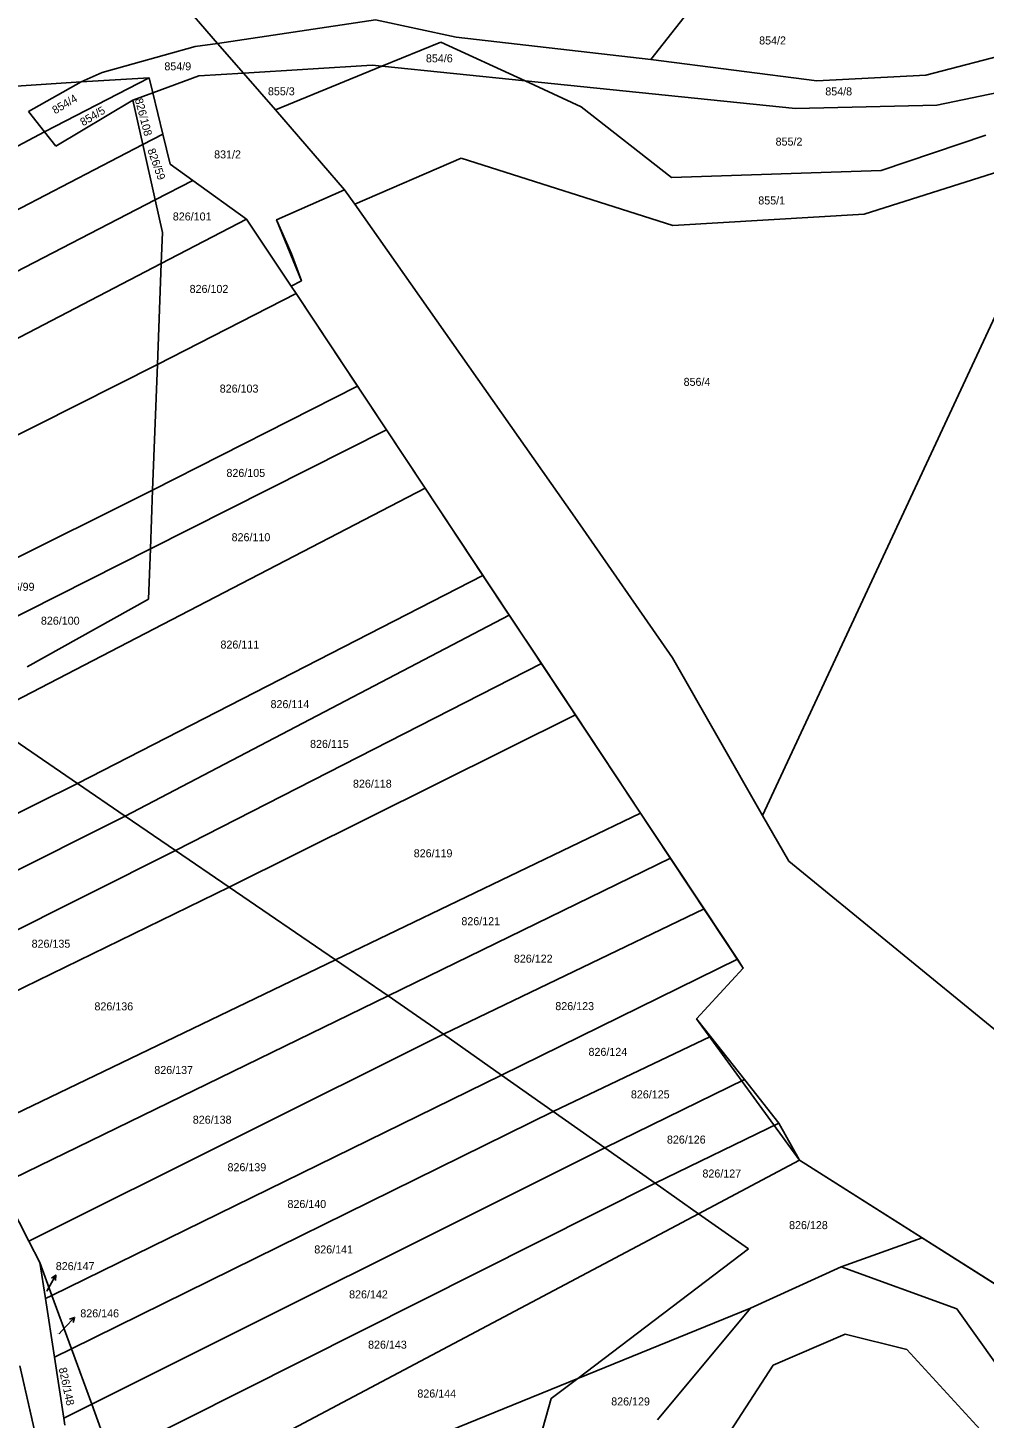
# Model space of a CAD drawing. Extents: x -593358 to -590116, y -1072518 to -1068420.
# Drawn here: x -592835.7 to -592632.7, y -1070925.3 to -1070630 of the extents above; entities that cross this region are included whole.
import ezdxf

# ---------------------------------------------------------------- set-up
doc = ezdxf.new("R2010")
doc.units = 0
for name, color, linetype in [('katastrální hranice', 7, 'Continuous'), ('lesy', 7, 'Continuous'), ('Parcela KN', 7, 'Continuous'), ('Parcela ZE', 7, 'Continuous'), ('Parcelní číslo', 7, 'Continuous'), ('vnější obvod_šetřený', 7, 'Continuous'), ('Vrstva 16', 7, 'Continuous')]:
    doc.layers.add(name, color=color, linetype=linetype)

msp = doc.modelspace()

# ---------------------------------------------------------------- linework, layer by layer
at = {"layer": 'katastrální hranice'}
msp.add_line((-592832.3, -1070936.59), (-592837.43, -1070914.17), dxfattribs=at)
at = {"layer": 'lesy'}
msp.add_line((-592778.79, -1070686.39), (-592779.83, -1070684.82), dxfattribs=at)
for points in [[(-592768.48, -1070664.38), (-592775.7, -1070667.555), (-592782.92, -1070670.73), (-592779.745, -1070677.95), (-592777.66, -1070683.7), (-592779.83, -1070684.82)], [(-592370.8, -1070941.28), (-592400.84, -1070929.68), (-592419.44, -1070939.96), (-592446.39, -1070946.25), (-592467.72, -1070944.19), (-592483.05, -1070937.18), (-592529.51, -1070942.3), (-592554.86, -1070932.86), (-592614.5, -1070906.86), (-592671.86, -1070870.49), (-592693.73, -1070840.44), (-592683.82, -1070829.7), (-592778.79, -1070686.39), (-592778.79, -1070686.39)]]:
    msp.add_lwpolyline(points, dxfattribs=at)
at = {"layer": 'Parcela KN'}
for p, q in [((-592814.19, -1070611.7), (-592795.43, -1070633.27)), ((-592688.83, -1070618.05), (-592703.45, -1070636.69)), ((-592795.43, -1070633.27), (-592761.93, -1070628.28)), ((-592744.82, -1070631.95), (-592761.93, -1070628.28)), ((-592645.05, -1070640.06), (-592598.34, -1070627.73)), ((-592795.43, -1070633.27), (-592800.23, -1070633.94)), ((-592703.45, -1070636.69), (-592744.82, -1070631.95)), ((-592800.23, -1070633.94), (-592819.94, -1070639.44)), ((-592789.95, -1070639.59), (-592762.64, -1070637.93)), ((-592762.64, -1070637.93), (-592760.55, -1070638.14)), ((-592760.55, -1070638.14), (-592730.16, -1070641.24)), ((-592703.45, -1070636.69), (-592668.22, -1070641.23)), ((-592840.32, -1070642.49), (-592824.4, -1070641.48)), ((-592824.4, -1070641.48), (-592835.61, -1070647.78)), ((-592819.94, -1070639.44), (-592824.4, -1070641.48)), ((-592809.19, -1070643.8), (-592799.44, -1070640.17)), ((-592799.44, -1070640.17), (-592789.95, -1070639.59)), ((-592789.95, -1070639.59), (-592783.18, -1070647.4)), ((-592730.16, -1070641.24), (-592672.73, -1070647.11)), ((-592668.22, -1070641.23), (-592645.05, -1070640.06)), ((-592642.73, -1070646.39), (-592617.04, -1070641.03)), ((-592813.42, -1070645.37), (-592809.19, -1070643.8)), ((-592807.05, -1070652.56), (-592809.19, -1070643.8)), ((-592835.61, -1070647.78), (-592832.17, -1070652.1)), ((-592829.78, -1070655.1), (-592813.42, -1070645.37)), ((-592813.42, -1070645.37), (-592811.32, -1070654.78)), ((-592783.18, -1070647.4), (-592768.48, -1070664.38)), ((-592672.73, -1070647.11), (-592642.73, -1070646.39)), ((-592832.17, -1070652.1), (-592829.78, -1070655.1)), ((-592805.49, -1070658.95), (-592807.05, -1070652.56)), ((-592811.32, -1070654.78), (-592808.7, -1070666.5)), ((-592800.73, -1070662.38), (-592805.49, -1070658.95)), ((-592743.74, -1070657.65), (-592766.33, -1070667.44)), ((-592698.8, -1070671.94), (-592743.74, -1070657.65)), ((-592789.31, -1070670.6), (-592800.73, -1070662.38)), ((-592629.39, -1070660.44), (-592658.18, -1070669.56)), ((-592768.48, -1070664.38), (-592782.92, -1070670.73)), ((-592768.48, -1070664.38), (-592766.33, -1070667.44)), ((-592808.7, -1070666.5), (-592807.14, -1070673.46)), ((-592766.33, -1070667.44), (-592719.62, -1070733.92)), ((-592779.83, -1070684.82), (-592789.31, -1070670.6)), ((-592782.92, -1070670.73), (-592777.66, -1070683.7)), ((-592658.18, -1070669.56), (-592698.8, -1070671.94)), ((-592807.14, -1070673.46), (-592807.39, -1070680.01)), ((-592807.39, -1070680.01), (-592808.2, -1070701.51)), ((-592777.66, -1070683.7), (-592779.83, -1070684.82)), ((-592779.83, -1070684.82), (-592778.79, -1070686.39)), ((-592778.79, -1070686.39), (-592765.73, -1070706.1)), ((-592808.2, -1070701.51), (-592809.23, -1070728.16)), ((-592765.73, -1070706.1), (-592759.61, -1070715.34)), ((-592759.61, -1070715.34), (-592751.39, -1070727.74)), ((-592751.39, -1070727.74), (-592739.1, -1070746.28)), ((-592809.23, -1070728.16), (-592809.7, -1070740.64)), ((-592719.62, -1070733.92), (-592698.84, -1070763.82)), ((-592809.7, -1070740.64), (-592810.11, -1070751.36)), ((-592739.1, -1070746.28), (-592733.5, -1070754.73)), ((-592810.11, -1070751.36), (-592835.85, -1070765.67)), ((-592733.5, -1070754.73), (-592726.68, -1070765.02)), ((-592726.68, -1070765.02), (-592719.48, -1070775.89)), ((-592698.84, -1070763.82), (-592679.76, -1070797.26)), ((-592825.15, -1070790.5), (-592845.5, -1070776.58)), ((-592719.48, -1070775.89), (-592705.62, -1070796.8)), ((-592815.08, -1070797.39), (-592825.15, -1070790.5)), ((-592804.37, -1070804.72), (-592815.08, -1070797.39)), ((-592705.62, -1070796.8), (-592699.28, -1070806.36)), ((-592679.76, -1070797.26), (-592674.19, -1070807.01)), ((-592792.97, -1070812.52), (-592804.37, -1070804.72)), ((-592699.28, -1070806.36), (-592692.16, -1070817.1)), ((-592674.19, -1070807.01), (-592629.89, -1070843.2)), ((-592770.39, -1070827.96), (-592792.97, -1070812.52)), ((-592692.16, -1070817.1), (-592685.06, -1070827.82)), ((-592759.25, -1070835.58), (-592770.39, -1070827.96)), ((-592685.06, -1070827.82), (-592683.82, -1070829.7)), ((-592683.82, -1070829.7), (-592693.73, -1070840.44)), ((-592754.1, -1070839.11), (-592759.25, -1070835.58)), ((-592747.5, -1070843.75), (-592754.1, -1070839.11)), ((-592693.73, -1070840.44), (-592690.76, -1070844.22)), ((-592735.19, -1070852.41), (-592747.5, -1070843.75)), ((-592690.76, -1070844.22), (-592683.56, -1070853.35)), ((-592724.18, -1070860.16), (-592735.19, -1070852.41)), ((-592683.56, -1070853.35), (-592676.25, -1070862.63)), ((-592713.22, -1070867.87), (-592724.18, -1070860.16)), ((-592676.25, -1070862.63), (-592671.86, -1070870.49)), ((-592702.55, -1070875.37), (-592713.22, -1070867.87)), ((-592671.86, -1070870.49), (-592645.86, -1070886.98)), ((-592693.32, -1070881.86), (-592702.55, -1070875.37)), ((-592835.52, -1070887.66), (-592841.69, -1070875.75)), ((-592682.7, -1070889.33), (-592693.32, -1070881.86)), ((-592645.86, -1070886.98), (-592614.5, -1070906.86)), ((-592833.16, -1070892.21), (-592835.52, -1070887.66)), ((-592718.96, -1070916.83), (-592682.7, -1070889.33)), ((-592833.16, -1070892.21), (-592830.61, -1070899.2)), ((-592831.98, -1070899.87), (-592833.16, -1070892.21)), ((-592682.28, -1070901.89), (-592663.07, -1070893.11)), ((-592663.07, -1070893.11), (-592638.47, -1070902.03)), ((-592830.07, -1070912.31), (-592831.98, -1070899.87)), ((-592830.61, -1070899.2), (-592826.46, -1070910.55)), ((-592702.07, -1070925.64), (-592682.28, -1070901.89)), ((-592638.47, -1070902.03), (-592623.05, -1070923.78)), ((-592677.46, -1070914), (-592662.19, -1070907.44)), ((-592662.19, -1070907.44), (-592649.13, -1070910.72)), ((-592826.46, -1070910.55), (-592822.17, -1070922.3)), ((-592649.13, -1070910.72), (-592621.72, -1070940.48)), ((-592828.08, -1070925.25), (-592830.07, -1070912.31)), ((-592724.64, -1070921.14), (-592718.96, -1070916.83)), ((-592677.46, -1070914), (-592692.75, -1070937.56)), ((-592822.17, -1070922.3), (-592818.1, -1070933.46)), ((-592738.55, -1070970.14), (-592724.64, -1070921.14)), ((-592827.84, -1070926.78), (-592828.08, -1070925.25))]:
    msp.add_line(p, q, dxfattribs=at)
at = {"layer": 'Parcela ZE'}
for p, q in [((-592795.43, -1070633.27), (-592789.95, -1070639.59)), ((-592748.05, -1070633.03), (-592760.55, -1070638.14)), ((-592730.16, -1070641.24), (-592748.05, -1070633.03)), ((-592760.55, -1070638.14), (-592783.18, -1070647.4)), ((-592832.17, -1070652.1), (-592809.98, -1070640.57)), ((-592824.4, -1070641.48), (-592809.98, -1070640.57)), ((-592809.98, -1070640.57), (-592809.19, -1070643.8)), ((-592718.23, -1070646.72), (-592730.16, -1070641.24)), ((-592606.92, -1070640.8), (-592679.76, -1070797.26)), ((-592699.07, -1070661.8), (-592718.23, -1070646.72)), ((-592959.9, -1070719.35), (-592832.17, -1070652.1)), ((-592811.32, -1070654.78), (-592807.05, -1070652.56)), ((-592632.31, -1070652.79), (-592654.56, -1070660.28)), ((-592952.08, -1070727.97), (-592811.32, -1070654.78)), ((-592808.7, -1070666.5), (-592800.73, -1070662.38)), ((-592654.56, -1070660.28), (-592699.07, -1070661.8)), ((-592945.68, -1070737.38), (-592808.7, -1070666.5)), ((-592807.39, -1070680.01), (-592789.31, -1070670.6)), ((-592938.93, -1070748.45), (-592807.39, -1070680.01)), ((-592808.2, -1070701.51), (-592778.79, -1070686.39)), ((-592897.8, -1070746.67), (-592808.2, -1070701.51)), ((-592809.23, -1070728.16), (-592765.73, -1070706.1)), ((-592809.7, -1070740.64), (-592759.61, -1070715.34)), ((-592845.5, -1070776.58), (-592751.39, -1070727.74)), ((-592874.2, -1070760.59), (-592809.23, -1070728.16)), ((-592852.99, -1070762.5), (-592809.7, -1070740.64)), ((-592739.1, -1070746.28), (-592825.15, -1070790.5)), ((-592733.5, -1070754.73), (-592815.08, -1070797.39)), ((-592804.37, -1070804.72), (-592726.68, -1070765.02)), ((-592792.97, -1070812.52), (-592719.48, -1070775.89)), ((-592825.15, -1070790.5), (-592876.55, -1070815.8)), ((-592815.08, -1070797.39), (-592870.28, -1070825.11)), ((-592770.39, -1070827.96), (-592705.62, -1070796.8)), ((-592863.9, -1070834.59), (-592804.37, -1070804.72)), ((-592759.25, -1070835.58), (-592699.28, -1070806.36)), ((-592858.04, -1070844.18), (-592792.97, -1070812.52)), ((-592747.5, -1070843.75), (-592692.16, -1070817.1)), ((-592847.28, -1070864.95), (-592770.39, -1070827.96)), ((-592685.06, -1070827.82), (-592735.19, -1070852.41)), ((-592841.69, -1070875.75), (-592759.25, -1070835.58)), ((-592835.52, -1070887.66), (-592747.5, -1070843.75)), ((-592690.76, -1070844.22), (-592724.18, -1070860.16)), ((-592735.19, -1070852.41), (-592830.61, -1070899.2)), ((-592683.56, -1070853.35), (-592713.22, -1070867.87)), ((-592724.18, -1070860.16), (-592826.46, -1070910.55)), ((-592676.25, -1070862.63), (-592702.55, -1070875.37)), ((-592713.22, -1070867.87), (-592822.17, -1070922.3)), ((-592671.86, -1070870.49), (-592693.32, -1070881.86)), ((-592702.55, -1070875.37), (-592818.1, -1070933.46)), ((-592693.32, -1070881.86), (-592813.66, -1070945.62)), ((-592663.07, -1070893.11), (-592645.86, -1070886.98)), ((-592830.61, -1070899.2), (-592831.98, -1070899.87)), ((-592718.96, -1070916.83), (-592682.28, -1070901.89)), ((-592826.46, -1070910.55), (-592830.07, -1070912.31)), ((-592774.9, -1070939.62), (-592718.96, -1070916.83)), ((-592822.17, -1070922.3), (-592828.08, -1070925.25))]:
    msp.add_line(p, q, dxfattribs=at)
at = {"layer": 'vnější obvod_šetřený'}
msp.add_line((-592837.43, -1070914.17), (-592834.865, -1070925.38), dxfattribs=at)
at = {"layer": 'Vrstva 16'}
for p, q in [((-592829.795, -1070894.908), (-592831.27, -1070897.52)), ((-592831.71, -1070898.31), (-592831.27, -1070897.52)), ((-592825.818, -1070903.871), (-592827.87, -1070906.06)), ((-592829.11, -1070907.38), (-592827.87, -1070906.06))]:
    msp.add_line(p, q, dxfattribs=at)
for points in [[(-592830.722, -1070895.533), (-592829.795, -1070894.908), (-592829.851, -1070896.025)], [(-592826.867, -1070904.259), (-592825.818, -1070903.871), (-592826.137, -1070904.943)]]:
    msp.add_lwpolyline(points, dxfattribs=at)

# ---------------------------------------------------------------- texts
at = {"layer": 'Parcelní číslo'}
for s, height, p in [('854/2', 1.7, (-592680.46, -1070633.51)), ('854/6', 1.7, (-592751.207, -1070637.3)), ('854/9', 1.7, (-592806.737, -1070639)), ('855/3', 1.7, (-592784.751, -1070644.3)), ('854/8', 1.7, (-592666.417, -1070644.33)), ('855/2', 1.7, (-592676.967, -1070654.99)), ('831/2', 1.7, (-592796.173, -1070657.71)), ('855/1', 1.7, (-592680.646, -1070667.49)), ('826/101', 1.7, (-592804.943, -1070670.89)), ('826/102', 1.7, (-592801.375, -1070686.28)), ('856/4', 1.7, (-592696.497, -1070706.02)), ('826/103', 1.7, (-592794.988, -1070707.45)), ('826/105', 1.7, (-592793.558, -1070725.36)), ('826/110', 1.7, (-592792.463, -1070739.02)), ('826/99', 1.7, (-592841.263, -1070749.54)), ('826/100', 1.7, (-592832.948, -1070756.75)), ('826/111', 1.7, (-592794.828, -1070761.82)), ('826/114', 1.7, (-592784.196, -1070774.47)), ('826/115', 1.7, (-592775.803, -1070782.92)), ('826/118', 1.7, (-592766.696, -1070791.37)), ('826/119', 1.7, (-592753.796, -1070806.15)), ('826/121', 1.7, (-592743.68, -1070820.58)), ('826/135', 1.7, (-592834.928, -1070825.36)), ('826/122', 1.7, (-592732.531, -1070828.53)), ('826/136', 1.7, (-592821.581, -1070838.67)), ('826/123', 1.7, (-592723.735, -1070838.62)), ('826/124', 1.7, (-592716.688, -1070848.33)), ('826/137', 1.7, (-592808.871, -1070852.18)), ('826/125', 1.7, (-592707.685, -1070857.36)), ('826/138', 1.7, (-592800.701, -1070862.74)), ('826/126', 1.7, (-592700.038, -1070866.96)), ('826/139', 1.7, (-592793.331, -1070872.83)), ('826/127', 1.7, (-592692.498, -1070874.17)), ('826/140', 1.7, (-592780.601, -1070880.64)), ('826/128', 1.7, (-592674.108, -1070885.13)), ('826/141', 1.7, (-592774.906, -1070890.3)), ('826/147', 0.1, (-592831.976, -1070898.31)), ('826/142', 1.7, (-592767.518, -1070899.84)), ('826/146', 0.1, (-592829.378, -1070907.38)), ('826/143', 1.7, (-592763.491, -1070910.52)), ('826/144', 1.7, (-592753.024, -1070920.9)), ('826/129', 1.7, (-592711.868, -1070922.58))]:
    msp.add_text(s, height=height, dxfattribs=at).set_placement(p)
for s, rotation, p in [('854/4', 30.82513, (-592829.921, -1070648.367)), ('826/108', 284.70273, (-592813.02, -1070645.16)), ('854/5', 30.76783, (-592823.993, -1070650.908)), ('826/59', 289.51558, (-592810.366, -1070655.926)), ('826/148', 282.18171, (-592829.187, -1070914.709))]:
    msp.add_text(s, height=1.7, rotation=rotation, dxfattribs=at).set_placement(p)
at = {"layer": 'Vrstva 16'}
for s, p in [('826/147', (-592829.793, -1070893.84)), ('826/146', (-592824.583, -1070903.87))]:
    msp.add_text(s, height=1.7, dxfattribs=at).set_placement(p)

doc.saveas('drawing.dxf')
